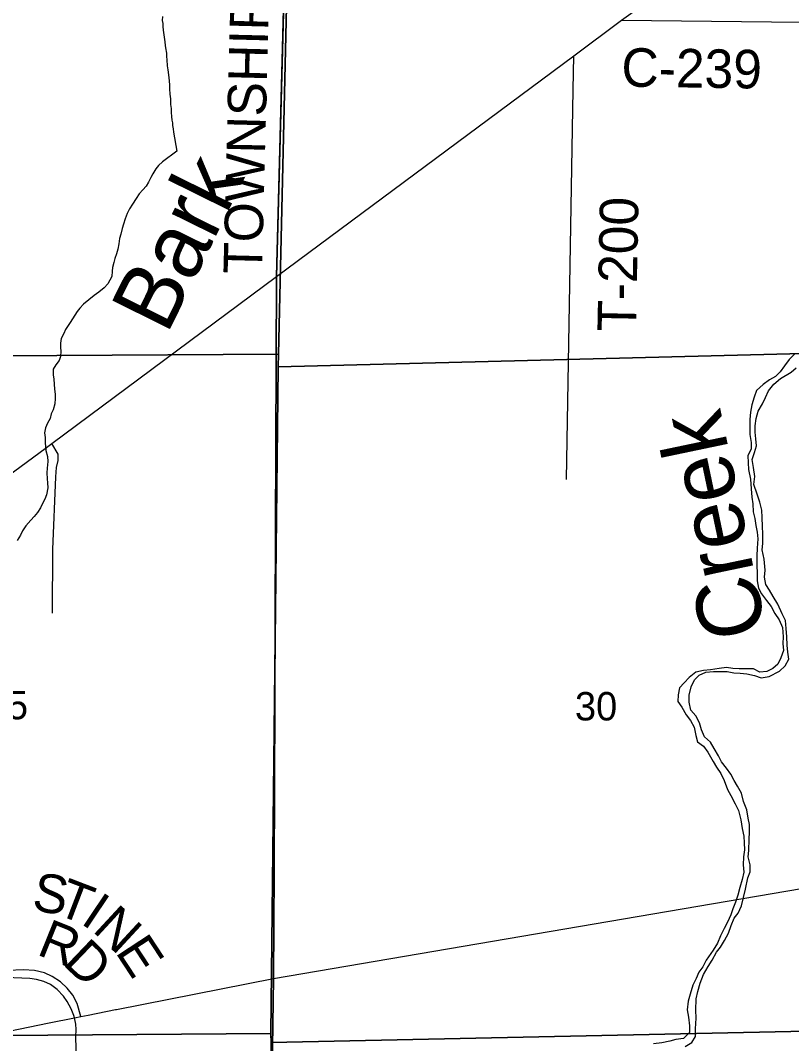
# Model space of a CAD drawing. Extents: x 1588073 to 2013523, y 1090242 to 1357120.
# Drawn here: x 1810221 to 1816219, y 1223082 to 1231039 of the extents above; entities that cross this region are included whole.
import ezdxf

# ---------------------------------------------------------------- set-up
doc = ezdxf.new("R2010")
doc.units = 0
for name, color, linetype in [('GM_X_County_Road', 7, 'Continuous'), ('GM_X_County_Road_Text', 7, 'Continuous'), ('GM_X_Interchange_Ramps', 7, 'Continuous'), ('GM_X_Minor_River', 7, 'Continuous'), ('GM_X_Minor_River_Text', 7, 'Continuous'), ('GM_X_Section', 7, 'Continuous'), ('GM_X_Section_Text', 7, 'Continuous'), ('GM_X_State_Route', 7, 'Continuous'), ('GM_X_Township', 7, 'Continuous'), ('GM_X_Township_Road', 7, 'Continuous'), ('GM_X_Township_Road_Text', 7, 'Continuous'), ('GM_X_US_Route', 7, 'Continuous')]:
    doc.layers.add(name, color=color, linetype=linetype)

msp = doc.modelspace()

# ---------------------------------------------------------------- linework, layer by layer
at = {"layer": 'GM_X_County_Road'}
for points in [[(1812212.5, 1229047), (1812294.3, 1232116.5)], [(1814895.7, 1231041.5), (1816295.9, 1231026.1), (1820037.2, 1231138.2), (1822397.6, 1231176.1), (1822544, 1231159.8), (1822713.9, 1231105.1), (1823174.2, 1231128.5), (1823644.2, 1231133.7), (1823903.7, 1231166.1), (1825222.2, 1231233.3), (1827893.8, 1231262.6)], [(1812193.6, 1224421.1), (1812212.5, 1229047)], [(1812190.2, 1223589.5), (1812193.6, 1224421.1), (1812193.6, 1224421.1)], [(1812163.8, 1220312.2), (1812142.7, 1220364.3), (1812190.2, 1223589.5)]]:
    msp.add_lwpolyline(points, dxfattribs=at)
at = {"layer": 'GM_X_Interchange_Ramps'}
for points in [[(1810641, 1223283), (1810637.3, 1223301.3), (1810617, 1223353.6), (1810585.9, 1223408.5), (1810555.6, 1223451), (1810506.8, 1223503.3), (1810456, 1223541.1), (1810403.3, 1223564.2), (1810346.1, 1223581.7), (1810294.9, 1223588.5), (1810170.4, 1223593.9), (1810097.7, 1223597.4), (1810046.2, 1223601.8), (1809987.7, 1223618.2), (1809936.1, 1223631.3), (1809877.9, 1223650.2), (1809770.6, 1223707.3), (1809666.5, 1223605.3)], [(1810580.1, 1222372.6), (1810690.4, 1222431.4), (1810687, 1222441.4), (1810661.4, 1222537.8), (1810647.6, 1222638.8), (1810644.1, 1222743.4), (1810654.5, 1223044.6), (1810653, 1223135.3), (1810654.2, 1223190.9), (1810651, 1223232.3), (1810641, 1223283)]]:
    msp.add_lwpolyline(points, dxfattribs=at)
at = {"layer": 'GM_X_Minor_River'}
for points in [[(1811325.3, 1231069.3), (1811324.8, 1231039.2), (1811328.4, 1231017), (1811328, 1230992.9), (1811331.5, 1230964.7), (1811336.9, 1230928.4), (1811338.5, 1230908.3), (1811343.9, 1230872), (1811347.5, 1230845.8), (1811349.1, 1230825.7), (1811356.5, 1230785.4), (1811356, 1230759.3), (1811359.6, 1230733.1), (1811362.8, 1230686.8), (1811368.3, 1230656.5), (1811371.6, 1230616.3), (1811375.2, 1230592.1), (1811376.8, 1230569.9), (1811380.2, 1230535.7), (1811381.7, 1230507.5), (1811383, 1230467.3), (1811388.4, 1230431), (1811389.6, 1230386.8), (1811393.1, 1230354.6), (1811394.5, 1230322.4), (1811396, 1230292.2), (1811399.5, 1230264), (1811403.2, 1230243.8), (1811404.8, 1230223.7), (1811408.4, 1230197.5), (1811411.9, 1230169.3), (1811437.6, 1230022.3)], [(1811437.6, 1230022.3), (1811326, 1229940), (1811295.6, 1229912.3), (1811275.3, 1229884.4), (1811250.8, 1229846.6), (1811236.5, 1229818.7), (1811216, 1229780.8), (1811199.6, 1229750.9), (1811173.3, 1229723.2), (1811144.9, 1229691.4), (1811120.4, 1229653.6), (1811091.9, 1229609.8), (1811069.4, 1229573.9), (1811051, 1229538.1), (1811034.5, 1229496.1), (1811022, 1229456.2), (1811011.6, 1229420.2), (1811001.1, 1229376.2), (1810992.7, 1229342.3), (1810986.2, 1229302.2), (1810977.7, 1229260.2), (1810967.3, 1229224.3), (1810954.9, 1229188.3), (1810948.5, 1229156.3), (1810938.1, 1229118.3), (1810935.7, 1229090.3), (1810931.3, 1229048.3), (1810916.9, 1229018.4), (1810900.6, 1228990.5), (1810872.1, 1228958.7), (1810831.7, 1228925.1), (1810793.4, 1228899.4), (1810712.5, 1228832.1), (1810682.1, 1228802.4), (1810661.7, 1228774.6), (1810643.4, 1228746.7), (1810606.7, 1228689), (1810572, 1228635.2), (1810557.7, 1228605.3), (1810539.2, 1228565.4), (1810532.8, 1228529.4), (1810532.4, 1228495.3), (1810534.1, 1228467.2), (1810533.6, 1228425.2), (1810521.2, 1228395.2), (1810496.8, 1228361.4), (1810476.4, 1228327.6), (1810475.8, 1228279.5), (1810481.5, 1228251.3), (1810483.1, 1228209.2), (1810486.7, 1228175.1), (1810492.2, 1228131), (1810491.8, 1228098.9), (1810489.4, 1228058.8), (1810474.8, 1228010.9), (1810460.4, 1227979), (1810452, 1227943), (1810431.6, 1227907.1), (1810415.1, 1227871.2), (1810408.7, 1227833.2), (1810414.3, 1227797.1), (1810413.8, 1227755), (1810415.5, 1227724.9), (1810419.1, 1227694.8), (1810430.6, 1227648.6), (1810434.2, 1227610.4), (1810429.6, 1227556.4), (1810427.2, 1227520.3), (1810428.6, 1227474.2), (1810432.3, 1227442.1), (1810433.8, 1227404), (1810423.2, 1227350), (1810410.8, 1227316), (1810390.3, 1227276.2), (1810376, 1227248.3), (1810353.5, 1227212.4), (1810327.1, 1227180.6), (1810300.8, 1227152.9), (1810264.2, 1227109.2), (1810237.8, 1227069.3), (1810221.3, 1227035.5), (1810194.9, 1226995.7)], [(1816246.7, 1228448.6), (1816199.4, 1228401.8), (1816164, 1228352.6), (1816130.7, 1228305.4), (1816093.7, 1228270.3), (1816047, 1228245.6), (1815997.9, 1228208.8), (1815946.6, 1228162.1), (1815929.2, 1228108.5), (1815909.5, 1228048.8), (1815900, 1227993), (1815894.4, 1227935), (1815894.8, 1227872.8), (1815895.3, 1227818.7), (1815905.7, 1227758.2), (1815904.3, 1227706.1), (1815878.9, 1227656.7), (1815881.3, 1227598.5), (1815883.9, 1227546.3), (1815899.9, 1227471.7), (1815903.9, 1227395.4), (1815910.1, 1227331.1), (1815916.7, 1227278.8), (1815921.1, 1227216.5)], [(1815885.9, 1224585.1), (1815890.2, 1224671.1), (1815891.8, 1224727.2), (1815891.3, 1224785.4), (1815880.7, 1224835.8), (1815870.4, 1224900.2), (1815846.1, 1224965.1), (1815829.9, 1225029.7), (1815799.3, 1225084.6), (1815772.5, 1225129.5), (1815745.8, 1225178.3), (1815713, 1225223.3), (1815674.2, 1225272.5), (1815651.5, 1225319.3), (1815617, 1225378.4), (1815588.3, 1225427.3), (1815541.4, 1225468.6), (1815518.8, 1225521.4), (1815504.2, 1225575.9), (1815475.7, 1225630.8), (1815436.8, 1225674), (1815422.5, 1225736.6), (1815422, 1225792.7), (1815437.7, 1225856.4), (1815463.3, 1225911.9), (1815500.3, 1225946.9), (1815553, 1225971.6), (1815611.2, 1225976), (1815667.2, 1225976.4), (1815719.3, 1225977), (1815769.1, 1225965.6), (1815819, 1225962.2), (1815871, 1225956.8), (1815930.7, 1225945.1), (1815982.2, 1225925.7), (1816044.6, 1225936), (1816125.8, 1225977.9), (1816169, 1226020.8), (1816198.4, 1226072.1), (1816189.9, 1226126.5), (1816185.4, 1226180.7), (1816183.1, 1226244.9), (1816176.8, 1226309.3), (1816172.5, 1226371.5), (1816145.9, 1226424.4), (1816111.9, 1226499.5), (1816075.5, 1226558.7), (1816046.7, 1226607.6), (1816017.9, 1226652.5), (1816007.4, 1226708.9), (1816012.9, 1226762.9), (1816005.2, 1226849.3), (1815991.2, 1226921.9), (1815994.5, 1226971.9), (1815996.5, 1227046), (1815992.1, 1227104.3), (1815990, 1227174.5), (1815987.5, 1227230.7), (1815971.2, 1227293.3), (1815950.9, 1227356), (1815926.8, 1227430.9), (1815934.5, 1227492.8), (1815922.4, 1227561.3), (1815912, 1227623.7), (1815931.6, 1227679.3), (1815947, 1227731), (1815942.4, 1227785.3), (1815935.8, 1227837.6), (1815937.2, 1227887.7), (1815942.7, 1227943.7), (1815958.3, 1228001.4), (1815993.8, 1228056.6), (1816017.2, 1228106), (1816038.6, 1228157.6), (1816080.1, 1228210.6), (1816133.4, 1228255.2), (1816214.8, 1228305.1), (1816255.7, 1228338.1)], [(1815921.1, 1227216.5), (1815933.7, 1227166), (1815940.2, 1227111.7), (1815952.8, 1227059.2), (1815957.4, 1227007), (1815951.5, 1226935), (1815947.8, 1226874.9), (1815948.1, 1226808.8), (1815952, 1226732.5), (1815952.7, 1226682.3), (1815963.1, 1226623.9), (1815985.9, 1226579.2), (1816024.6, 1226528), (1816059.3, 1226480.9), (1816087.9, 1226426), (1816122.6, 1226376.9), (1816149, 1226318.1), (1816155.1, 1226245.7), (1816151.7, 1226193.7), (1816156.2, 1226139.4), (1816136.6, 1226081.8), (1816111.3, 1226032.4), (1816072.3, 1225999.4), (1816025.7, 1225976.6), (1815973.5, 1225972), (1815924.1, 1225997.4), (1815868, 1225997), (1815812, 1225996.5), (1815762, 1225999.9), (1815712.1, 1226007.3), (1815655.8, 1225998.8), (1815589.5, 1225988.6), (1815535.3, 1225984.1), (1815474.9, 1225969.7), (1815423.7, 1225929), (1815384.5, 1225888), (1815347.4, 1225848.9), (1815336, 1225795.1), (1815334.6, 1225743), (1815365.4, 1225698), (1815399.8, 1225638.9), (1815432.7, 1225595.9), (1815461.3, 1225543), (1815475.6, 1225478.5), (1815488.3, 1225430), (1815535.4, 1225394.6), (1815568.1, 1225347.6), (1815608.3, 1225276.3), (1815635.1, 1225231.5), (1815667.8, 1225182.5), (1815694.3, 1225127.6), (1815720.5, 1225058.7), (1815747.3, 1225011.9), (1815779.6, 1224946.8), (1815806.2, 1224894), (1815824.3, 1224823.3), (1815834.4, 1224754.9), (1815846.9, 1224696.4), (1815851.5, 1224644.1), (1815853.9, 1224587.9), (1815844.5, 1224534.1), (1815842.8, 1224471.9), (1815847.3, 1224415.7), (1815833.7, 1224357.9), (1815818, 1224296.2), (1815800.4, 1224236.5), (1815782.9, 1224182.9), (1815763.5, 1224131.3), (1815746.2, 1224083.7), (1815720.6, 1224026.2), (1815695.3, 1223976.8), (1815667.7, 1223919.4), (1815644.1, 1223861.9), (1815610.6, 1223808.7), (1815554.4, 1223730.1), (1815529, 1223678.6), (1815497.9, 1223637.4), (1815476.5, 1223587.8), (1815451.1, 1223536.4), (1815429.2, 1223466.8), (1815415.7, 1223413.1), (1815407.9, 1223345.1), (1815418.3, 1223288.7), (1815424.5, 1223220.4), (1815425.1, 1223168.2), (1815377.8, 1223121.4), (1815319.5, 1223115), (1815271.1, 1223100.3), (1815210.7, 1223087.9), (1815146.4, 1223079.7)], [(1815392.1, 1223058.9), (1815443, 1223091.6), (1815472.3, 1223136.9), (1815471.9, 1223197), (1815476.1, 1223279.1), (1815475.8, 1223341.3), (1815478.2, 1223429.4), (1815489.8, 1223487.2), (1815507.6, 1223552.9), (1815535.4, 1223618.3), (1815571.1, 1223681.5), (1815602.5, 1223730.7), (1815636.2, 1223792), (1815665.3, 1223833.3), (1815698.8, 1223884.5), (1815728.3, 1223941.8), (1815749.9, 1223999.3), (1815773.5, 1224056.8), (1815804.6, 1224096.1), (1815830.2, 1224153.5), (1815846, 1224219.2), (1815859.7, 1224283), (1815878.1, 1224370.7), (1815897.4, 1224418.3), (1815896.9, 1224472.5), (1815882.5, 1224535), (1815885.9, 1224585.1)]]:
    msp.add_lwpolyline(points, dxfattribs=at)
at = {"layer": 'GM_X_Section'}
for points in [[(1807596.6, 1233740.8), (1812346.7, 1233625.2), (1812227.2, 1228444.3), (1807054, 1228412.1), (1807227.5, 1233599), (1807405.7, 1233609.9), (1807463.7, 1233609.5), (1807517.8, 1233623.2), (1807562.1, 1233658.9)], [(1812346.7, 1233625.2), (1817336.3, 1233708.2), (1817226.4, 1228473.5), (1812224.6, 1228344.3), (1812227.2, 1228444.3)], [(1817226.4, 1228473.5), (1817193.8, 1223196.6), (1812172.2, 1223091.5), (1812168.6, 1223159.6), (1812224.6, 1228344.3)], [(1812227.2, 1228444.3), (1812224.6, 1228344.3), (1812168.6, 1223159.6), (1806959.3, 1223121.7), (1807054, 1228412.1)], [(1812168.6, 1223159.6), (1812172.2, 1223091.5), (1812121.6, 1217818.8), (1806815.3, 1217935.6), (1806959.3, 1223121.7)], [(1817193.8, 1223196.6), (1817118.9, 1217888), (1816936.8, 1217887.1), (1812121.6, 1217818.8), (1812172.2, 1223091.5)]]:
    msp.add_lwpolyline(points, close=True, dxfattribs=at)
at = {"layer": 'GM_X_State_Route'}
for points in [[(1814910.8, 1224052.3), (1814912.7, 1224052.6), (1816296.7, 1224288)], [(1812190.2, 1223589.5), (1814910.8, 1224052.3)], [(1810961.5, 1223346.6), (1810968.9, 1223348), (1812190.2, 1223589.5)], [(1810444.8, 1223243.1), (1810641, 1223283), (1810689.8, 1223292.7), (1810747.8, 1223304.2)], [(1810747.8, 1223304.2), (1810961.5, 1223346.6)], [(1809912.3, 1223136.4), (1810052.4, 1223163.3), (1810444.8, 1223243.1)]]:
    msp.add_lwpolyline(points, dxfattribs=at)
at = {"layer": 'GM_X_Township'}
for points in [[(1810039.2, 1246329.4), (1810826.3, 1246175.2), (1811181.2, 1246113.6), (1811428.2, 1246129), (1811520.7, 1246144.5), (1811721.3, 1246268), (1811829.3, 1246484.1), (1812153.3, 1246746.5), (1812292.2, 1246978), (1812477.3, 1247255.9), (1812700.7, 1247387.3), (1812517.7, 1241446.2), (1812470.9, 1240258.4), (1812389.9, 1236007.7), (1812324.1, 1233316.7), (1812310.4, 1232757.7), (1812298.6, 1232275.3), (1812212.5, 1229047), (1812193.6, 1224421.1), (1812190.2, 1223589.5), (1812142.7, 1220364.3)], [(1812142.7, 1220364.3), (1812190.2, 1223589.5), (1812193.6, 1224421.1), (1812212.5, 1229047), (1812298.6, 1232275.3), (1812310.4, 1232757.7), (1812324.1, 1233316.7), (1812389.9, 1236007.7), (1812470.9, 1240258.4)]]:
    msp.add_lwpolyline(points, dxfattribs=at)
at = {"layer": 'GM_X_Township_Road'}
for points in [[(1814519.8, 1230498.7), (1814524.4, 1230764.4)], [(1814467.6, 1227469.3), (1814519.8, 1230498.7), (1814519.8, 1230498.7)], [(1810471.6, 1226430.3), (1810473.6, 1226925.7), (1810496.6, 1227489), (1810501.9, 1227563.1), (1810514.8, 1227617.1), (1810515.5, 1227667.2), (1810465.3, 1227749)], [(1810689.8, 1223292.7), (1810663.1, 1223395.1), (1810628.6, 1223458.3), (1810585.7, 1223513.5), (1810531.8, 1223563.4), (1810468.3, 1223604.8), (1810407.7, 1223631.7), (1810331.1, 1223651.3), (1810243.9, 1223656.8), (1810124.3, 1223649.9), (1810028.1, 1223647.4), (1809957.1, 1223659.5), (1809902.2, 1223674.8), (1809838.6, 1223704.6), (1809759.1, 1223751.5), (1809698.1, 1223806.7), (1809653.6, 1223861.5), (1809623.7, 1223914)]]:
    msp.add_lwpolyline(points, dxfattribs=at)
at = {"layer": 'GM_X_US_Route'}
for points in [[(1810422.8, 1227717.8), (1810465.3, 1227749), (1812212.5, 1229047), (1814524.4, 1230764.4), (1814895.7, 1231041.5), (1815919.2, 1231776.1), (1819197.3, 1234267.7), (1819277.8, 1234324.6), (1819315.1, 1234350.9)], [(1809572.9, 1227093.1), (1810422.8, 1227717.8)]]:
    msp.add_lwpolyline(points, dxfattribs=at)

# ---------------------------------------------------------------- texts
at = {"layer": 'GM_X_County_Road_Text'}
for s, rotation, p in [('TOWNSHIP', 88.5383, (1812099.6, 1229065.2)), ('C-239', 359.17413, (1814894.1, 1230525.4))]:
    msp.add_text(s, height=300, rotation=rotation, dxfattribs=at).set_placement(p)
at = {"layer": 'GM_X_Minor_River_Text'}
for s, height, rotation, p in [('Bark', 500.3, 63.67861, (1811360, 1228590)), ('Creek', 500.32, 101.81998, (1816028.4, 1226282.7))]:
    msp.add_text(s, height=height, rotation=rotation, dxfattribs=at).set_placement(p)
at = {"layer": 'GM_X_Section_Text'}
for s, p in [('25', (1809951.6, 1225604.1)), ('30', (1814534.2, 1225595.3))]:
    msp.add_text(s, height=221, rotation=0.00001, dxfattribs=at).set_placement(p)
at = {"layer": 'GM_X_Township_Road_Text'}
for s, rotation, p in [('T-200', 88.87623, (1815008.6, 1228616.4)), ('S', 350.74936, (1810302.9, 1224121.2)), ('T', 339.04018, (1810487.1, 1224092.9)), ('I', 326.11943, (1810680.8, 1224020.8)), ('N', 317.20671, (1810773.4, 1223959.8)), ('R', 337.97609, (1810339.6, 1223778.2)), ('E', 303.28357, (1810954.7, 1223795.1)), ('D', 316.27258, (1810543, 1223702))]:
    msp.add_text(s, height=300, rotation=rotation, dxfattribs=at).set_placement(p)

doc.saveas('drawing.dxf')
